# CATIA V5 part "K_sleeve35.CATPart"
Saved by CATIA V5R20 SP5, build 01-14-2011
Part number: sleeve35
Bounding box of the stored display mesh (mm): x -25 to 25, y -12 to 12, z -11.99 to 11.99
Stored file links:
  G:\Khaled_CFAO_2011\ST2M\ST2M_GR2\amorin\Khaled\CAD_Modification\K_sleeve35.CATPart
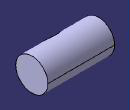
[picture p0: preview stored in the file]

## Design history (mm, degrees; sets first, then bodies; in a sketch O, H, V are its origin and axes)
Body1 (main body)
  Sketch1 on yz-plane, origin (0, 0, 0), H (0, 1, 0), V (0, 0, 1)
    circle A1 centre (0, 0) radius 12
  Pad1: profile Sketch1, direction (1, 0, 0), length 25, mirrored extent
  Sketch2 on zx-plane, origin (0, 0, 0), H (-1, 0, 0), V (0, 0, 1)
    circle A1 centre (0, 0) radius 10
    point P1 (10, 0)
    coincidence: A1 P1, P1 H
  Pad2: profile Sketch2, direction (0, -1, 0), length 13
  Sketch3 on end face of Pad2, origin (0, -13, 0), H (1, 0, 0), V (0, 0, 1)
    point P1 (0, 0)
  Hole1: placed by Sketch3, at (0, -13, 0) direction (0, 1, 0), diameter 20, depth 18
